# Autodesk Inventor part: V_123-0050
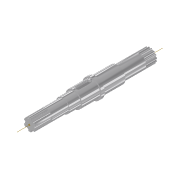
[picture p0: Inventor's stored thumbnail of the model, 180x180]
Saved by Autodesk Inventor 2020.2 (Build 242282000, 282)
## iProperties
+MSCProtocol1+ProtocolID: P00060228124250375
+MSCProtocol2+Protocol: P00060228124250375<@PID>[Version]<@EL>Version=2.0<@EL>[CalcData]<@EL>LastID=8<@EL>Gen=3<@EL>IsMCW=0<@EL>CalcResult=False<@EL>[Files]<@EL>DataFile=SpiData|shaft3
Manager: www.cadconsulting.pl
Company: Fabian Stasiak CAD Consulting
Created: 2004-04
Part Number: V_123-0050
Document SubType Name: Modeling
Manufacturer: Standard
Standards Organization: Custom
Description: Wałek
Material: Stal 45
Project: Przekładnia X51
Designer: F.Stasiak
Density: 7.85 g/cm^3
Appearance: Chrom
+MSCFeatProtocols1+FeatNameP00060309102124484: SPLINE2A2
+MSCFeatProtocols2+ProtocolIDP00060309102124484: P00060309102124484
+MSCFeatProtocols3+ProtocolP00060309102124484: P00060309102124484<@PID>[Version]<@EL>Version=2.2<@EL>[Object]<@EL>Description=Kreator wielowypustów ewolwentowych<@EL>ProtID=<@EL>Object=SPLINE2<@EL>[Synchroni
+MSCFeatProtocols4+FeatNameP00060309103342671: N014942B1
+MSCFeatProtocols5+ProtocolIDP00060309103342671: P00060309103342671
+MSCFeatProtocols6+ProtocolP00060309103342671: P00060309103342671<@PID>[Version]<@EL>Version=2.2<@EL>[Synchronize]<@EL>ChangedVars=<@EL>[Calc]<@EL>WizardMode=0<@EL>Version=10.3.272<@EL>Optim=1<@EL>CalcName=S
+MSCFeatProtocols7+FeatNameP00060309103511281: SPLINE2A3
+MSCFeatProtocols8+ProtocolIDP00060309103511281: P00060309103511281
+MSCFeatProtocols9+ProtocolP00060309103511281: P00060309103511281<@PID>[Version]<@EL>Version=2.2<@EL>[Files]<@EL>DataFile=SpiData|Evol<@EL>[Synchronize]<@EL>ChangedVars=<@EL>[Calc]<@EL>WizardMode=0<@EL>Versi
Author: F.Stasiak
Subject: Zbiór ćwiczeń. Autodesk Inventor 2020. Kurs podstawowy
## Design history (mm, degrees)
sketch "Szkic2"
  geometry: L1 (0, 0)-(219, 0) reference; L2 (0, 0)-(0, 11); L3 (0, 11)-(60, 11); L4 (60, 11)-(60, 12.5); L5 (60, 12.5)-(80, 12.5); L6 (80, 12.5)-(80, 15); L7 (80, 15)-(113, 15); L8 (113, 15)-(113, 17.5); L9 (119, 17.5)-(119, 15); L10 (113, 17.5)-(119, 17.5); L11 (159, 15)-(159, 12.5); L12 (119, 15)-(159, 15); L13 (219, 12.5)-(219, 0); L14 (159, 12.5)-(219, 12.5)
  constraints: 28 end point, 7 vertical, 2 horizontal
  dimensions: "d0" = 22 diameter of L3 L1 (derived); "d1" = 25 diameter of L5 L1 (derived); "d2" = 30 diameter of L7 L1 (derived); "d3" = 35 diameter of L10 L1 (derived); "d4" = 30 diameter of L12 L1 (derived); "d5" = 25 diameter of L14 L1 (derived)
revolve "Obrót1" sketch "Szkic2" stored, may be unused: angle "d6" = 0 deg
feature "Keyway1"
node "Oś konstrukcyjna1"
node "Punkt konstrukcyjny1"
sketch "Szkic6"
  geometry: L1 (0, 0.01)-(0, 11.01); L2 (0, 0.01)-(-9.526, 5.51); L3 (-2.5, 10.487)-(-2.5, 8.122); L4 (-7.824, 7.414)-(-5.776, 6.231); L5 (-7.824, 7.414)-(-8.234, 7.304); L6 (-2.5, 10.487)-(-2.2, 10.787); A1 r 0.2 centre (-5.676, 6.404) between (-5.776, 6.231) and (-5.543, 6.255); A2 r 0.2 centre (-2.7, 8.122) between (-2.637, 7.932) and (-2.5, 8.122); A3 r 8.35 centre (0, 0.01) between (-2.637, 7.932) and (-5.543, 6.255); A4 r 11 centre (0, 0.01) between (-2.2, 10.787) and (-8.234, 7.304); A5 r 11 centre (0, 0.01) between (0, 11.01) and (-9.526, 5.51); 1 further point
  constraints: 12 end point, 12 point on circle, 5 centre point, 3 tangent, 2 coincident, 2 equal length, 2 parallel, 2 point on line, 1 concentric, 1 equal radius, 1 vertical
  dimensions: "d83" = 60 deg angle of L1 L2 (derived); "d85" = 2.5 distance between parallel lines of L1 L3 (derived); "d90" = 16.7 diameter of A3 (derived); "d88" = 0.2 radius of A1 (derived); "d87" = 2.5 distance between parallel lines of L2 L4 (derived); "d92" = 0.3 distance from line of L6.end L3 (derived); "d95" = 45 deg angle of L3 L6; "d94" = 45 deg angle of L5 L4; "d96" = 22 diameter of A5 (derived)
feature "N014942B1" sketch "Szkic6"
node "Punkt konstrukcyjny2"
sketch "Szkic7"
  geometry: L1 (0, 0.051)-(0, 12.534); L2 (0, 0.051)-(2.256, 10.664); A1 r 5.355 centre (-3.35, 8.979) between (1.697, 10.768) and (0.654, 12.534); A2 r 10.85 centre (0, 0.051) between (1.697, 10.768) and (2.256, 10.664); A3 r 10.85 centre (0, 0.051) between (2.256, 10.664) and (1.697, 10.768); A4 r 12.5 centre (0, 0.051) between (2.599, 12.278) and (0.654, 12.534); A5 r 10.85 centre (0, 0.051) between (2.808, 10.532) and (2.256, 10.664); A6 r 5.355 centre (6.691, 6.845) between (4.48, 11.721) and (2.808, 10.532); A7 r 12.5 centre (0, 0.051) between (4.48, 11.721) and (2.599, 12.278); 1 further point
  constraints: 14 point on circle, 7 centre point, 5 coincident, 5 end point, 3 symmetric about line, 1 horizontal alignment, 1 point on line, 1 vertical, 3 other
  dimensions: "d98" = 5.35458 radius of A1 (= d99); "d124" = 21.7 diameter of A2 (= d110); "d123" = 3.34956 distance from line of A1.centre L1 (= d120); "d122" = 8.92738 vertical distance of L1.start A1.centre (= d100); "d125" = 12 deg angle of L2 L1 (computed from d105); "d126" = 25 diameter of A4 (= d108)
feature "SPLINE2A3" sketch "Szkic7"
node "Bryła1"
node "Korpusy bryłowe"
node "Korpusy powierzchniowe"
other parameters: "d99" = 5.35458 (computed from d121, d120, d100) [user parameter; used in 1 equation term], "d100" = 8.92738 (computed from d119, d118, d101) [user parameter; used in 4 equation terms], "d101" = 7.53362 (computed from d116, d115, d113, d102) [user parameter; used in 1 equation term], "d102" = -21.09261 (computed from d114, d113, d103) [user parameter; used in 2 equation terms], "d103" = -0.46736 (= d112 - d104) [user parameter; used in 2 equation terms], "d104" = -1.22995 (computed from d107, d105) [user parameter; used in 5 equation terms], "d107" = 11.76667 (= 0.222222 x d110 + 0.277778 x d108) [user parameter; used in 2 equation terms], "d108" = 25 [user parameter; used in 5 equation terms], "d110" = 21.7 [user parameter; used in 5 equation terms], "d112" = -1.69731 (computed from d110, d105) [user parameter; used in 2 equation terms], "d113" = 11.70221 (computed from d107, d105) [user parameter; used in 5 equation terms], "d114" = 10.71642 (computed from d110, d105) [user parameter; used in 2 equation terms], "d115" = 12.48287 (computed from d108, d105) [user parameter; used in 2 equation terms], "d116" = -0.57575 (= d104 - d117) [user parameter; used in 2 equation terms], "d117" = -0.6542 (computed from d108, d105) [user parameter; used in 2 equation terms], "d118" = 22.17973 (computed from d114, d112, d104, d113, d103) [user parameter; used in 2 equation terms], "d119" = 15.45418 (computed from d113, d104, d117, d115, d116) [user parameter; used in 1 equation term], "d120" = 3.34956 (computed from d118, d100, d102) [user parameter; used in 3 equation terms], "d121" = 6.22461 (computed from d104, d120, d113, d100) [user parameter; used in 1 equation term]
